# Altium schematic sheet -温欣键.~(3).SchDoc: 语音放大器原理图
size A4; Organization: 江门职业技术学院; Address1: 14电路设计1班; Address2: 温欣键; Address3: 学号：141806043; SheetNumber: 1; SheetTotal: 2
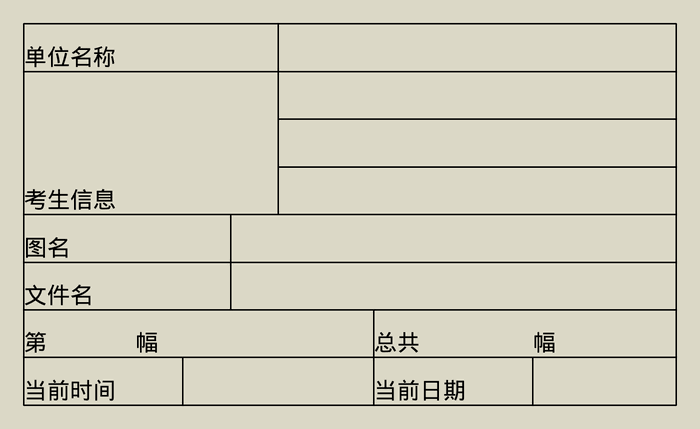
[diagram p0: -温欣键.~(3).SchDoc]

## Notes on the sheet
- 单位名称
- 考生信息
- 图名
- 文件名
- 第
- 幅
- 总共
- 当前时间
- 当前日期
